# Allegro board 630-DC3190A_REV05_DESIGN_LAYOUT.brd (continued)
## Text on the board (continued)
User.11: UNLESS OTHERWISE SPECIFIED | THIRD ANGLE PROJECTION | DIMENSIONS ARE IN INCHES | TOLERANCES: | INTERPRET DIM AND TOL | PER ASME Y14.5M-1994 | 0.XXX" =  0.005" | 0.XX" =  0.01" | - | + | .062" +/- 10% | 8 LAYERS | THICKNESS AS REQ'D | 0.028" | 0.005" | TITLE: | N/A | SIZE | www.analog.com | FABRICATION DRAWING | IC NO. | LAYER 1- PRIMARY SIDE | FR4 | LAYER 2 (GND) | LAYER 3 (ROUTE) | LAYER 4 (GND) | LAYER 5 (GND) | LAYER 6 (ROUTE) | LAYER 7 (GND) | LAYER 8- SECONDARY SIDE | FOR ADI CUSTOMER USE ONLY | P | O | W | SHT 1 OF 1 | E | R | B | Y | REV | TM | FINISHED HOLE TO | BE FILLED WITH | NON-CONDUCTIVE | EPOXY | Cu OVER HOLE | FILLED VIA (VIA IN PAD) | ADDITIONAL REQUREMENT FOR PROTOTYPE FAB ONLY: | ADDITIONAL REQUREMENTS FOR PRODUCTION FAB ONLY: | DRILL SYMBOL "X" | SOLDERSIDE | 1. OUTGOING INSPECTION REPORT (BASED ON ACTUAL MEASUREMENTS AND CROSS SECTION). | 1. PROVIDE COMPLIANCE CERTIFICATES FOR RoHS, REACH AND CONFLICT-FREE MINERALS. | 2. SOLDERABILITY BOARD WITH TEST RESULTS. | 3. OUTGOING INSPECTION REPORT (BASED ON ACTUAL MEASUREMENTS AND CROSS SECTION). | 4. VACUUM PACKED WITH DESICCANT. | 5. FULL PANEL WITH NO REJECT | 917 PLACES | COMPSIDE | (NOT TO SCALE) | WILL HAVE BOXES TO MARK WHICH VER. | NOTE: IC LTP88XX and DC3190A- * | REFER TO THE CORRESPONDING BOM | 2. MATERIAL: -EPOXY FIBERGLASS, FR-4, HIGH Tg180 | 5. FINISH: -SMOBC USING LPI BOTH SIDES, COLOR GLOSS GREEN | 6. DO NOT ALTER ARTWORK e.g. TO ADD LOGO OR DATE CODE. | 7. PCBS ARE TO BE RoHS COMPLIANT. | 8. SCORING FOR PANELIZED PCB: | 3. SIZE: CUT TO DIMENSIONS AND TOLERANCES SHOWN. | 4. DRILLING: -DRILL HOLES PER SCHEDULE. PLATE THROUGH | 1. FAB PER IPC-A-600. | PAD SIZE CAN BE MODIFIED TO MEET END FINISH. | 0.00" ARE PRIMARY DATUMS. | .017 | -GOLD IMMERSION BOTH SIDES. | -FOR SILKSCREEN: BOTH SIDES USE WHITE NON-CONDUCTIVE INK. | x | (LEAD FREE SOLDER CAN BE USED FOR PROTOTYPE) | -FOR VIAS SIZE LESS THAN 0.012", VIAS HOLES NEED | -ALL HOLE SIZES ARE SPECIFIED AFTER PLATING. | -HOLE LOCATION TOLERANCES ARE +/-0.003" | HOLES WITH COPPER, 0.001" THICK MIN. | IN RELATION TO CENTER | TO BE PLUGGED AND COVERED WITH SOLDERMASK. | -FINISHED THICKNESS TO BE 0.062" +/- .005" | -TOTAL OF 8 LAYERS WITH 2 OZ. CU ON THE OUTER LAYERS | -FLAMMABILITY RATING: 94 V-O MINIMUM. | AND 2 OZ. CU ON THE INNER LAYERS. | LAYER STRUCTURE | .020 | NOTES: UNLESS OTHERWISE SPECIFIED | 5 | 54V INPUT, HIGH CURRENT DC/DC | POWER MODULE WITH PMBUS INTERFACE | LTP88XX | DC3190A-*
User.12: FIGURE | FINISHED_SIZE | 9.8 | 10.0 | 40.0 | 51.0 | 59.0 | 65.0 | 195.0 | 215.0 | 70.0 | 187.0 | DRILL CHART: TOP to BOTTOM | ALL UNITS ARE IN MILS | TOLERANCE_DRILL | +3.0/-3.0 | PLATED | NON-PLATED | QTY | 917 | 414 | 7 | 2 | 8 | 12 | 4
User.15: E3 | E4 | E5 | E6 | E7 | E8 | E9 | E10 | J9 | J7 | J6 | J11 | J8 | J10 | E12 | E11 | E14 | E13
